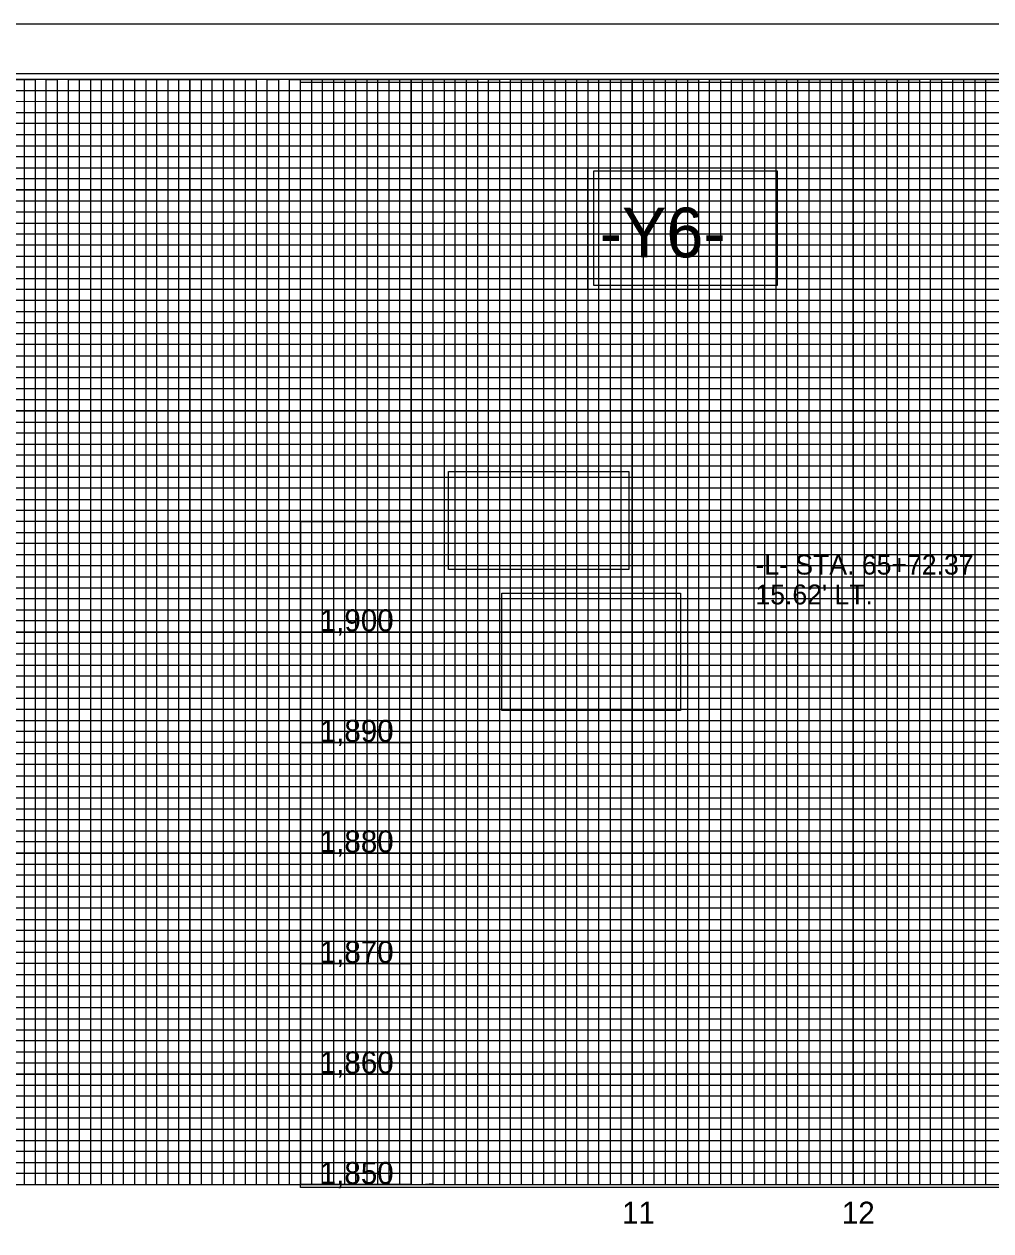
# Model space of a CAD drawing. Extents: x 557032 to 558716, y 525869 to 526969.
# Drawn here: x 557874 to 558312, y 526423 to 526969 of the extents above; entities that cross this region are included whole.
import ezdxf

# ---------------------------------------------------------------- set-up
doc = ezdxf.new("R2010")
doc.units = 0
for name, color, linetype in [('Exist Vertical Profile Horizontal Axis Label Major', 7, 'Continuous'), ('Exist Vertical Profile Vertical Axis Label', 7, 'Continuous'), ('Old_Level_63', 7, 'Continuous'), ('Prop Vertical Profile Curve Label', 7, 'Continuous'), ('Prop Vertical Profile Grade Label', 7, 'Continuous'), ('Prop VPI Label', 7, 'Continuous'), ('Scratch_Level_5', 7, 'Continuous'), ('Sheet Cutting Line CELL', 7, 'Continuous'), ('Sheet DOT Grid CELL', 7, 'Continuous'), ('Sheet Layout Profile Border Port 1', 7, 'Continuous'), ('Sheet Plot Border Inside CELL', 7, 'Continuous'), ('Sheet Plot Border Outside CELL', 7, 'Continuous'), ('Sheet Profile CELL', 7, 'Continuous'), ('Sheet Profile Grid Major CELL', 7, 'Continuous'), ('Sheet Profile Grid Middle CELL', 7, 'Continuous'), ('Sheet Profile Grid Minor CELL', 7, 'Continuous')]:
    doc.layers.add(name, color=color, linetype=linetype)

msp = doc.modelspace()

# ---------------------------------------------------------------- linework, layer by layer
at = {"layer": 'Old_Level_63'}
msp.add_lwpolyline([(557999.45, 526744.22), (558049.45, 526744.22), (558049.45, 526444.22), (557999.45, 526444.22)], close=True, dxfattribs=at)
at = {"layer": 'Prop Vertical Profile Curve Label'}
for points in [[(558132.11, 526902.85), (558215.04, 526902.85), (558215.04, 526850.91), (558132.11, 526850.91)], [(558132.11, 526902.85), (558215.04, 526902.85), (558215.04, 526850.91), (558132.11, 526850.91)], [(558066.42, 526766.81), (558148.02, 526766.81), (558148.02, 526722.46), (558066.42, 526722.46)], [(558090.5, 526711.86), (558171.26, 526711.86), (558171.26, 526658.64), (558090.5, 526658.64)]]:
    msp.add_lwpolyline(points, close=True, dxfattribs=at)
at = {"layer": 'Prop VPI Label'}
msp.add_lwpolyline([(558129.45, 526904.22), (558214.45, 526904.22), (558214.45, 526849.22), (558129.45, 526849.22)], close=True, dxfattribs=at)
at = {"layer": 'Scratch_Level_5'}
msp.add_lwpolyline([(557999.45, 526942.96), (558514.45, 526942.96), (558514.5, 526442.96), (557999.5, 526442.96)], close=True, dxfattribs=at)
at = {"layer": 'Sheet Cutting Line CELL'}
msp.add_line((558716.45, 526969.22), (557032.45, 526969.22), dxfattribs=at)
at = {"layer": 'Sheet DOT Grid CELL'}
for p, q in [((557899.45, 526444.22), (557899.45, 526944.22)), ((557949.45, 526444.22), (557949.45, 526944.22)), ((557999.45, 526444.22), (557999.45, 526944.22)), ((558049.45, 526444.22), (558049.45, 526944.22)), ((558099.45, 526444.22), (558099.45, 526944.22)), ((558149.45, 526444.22), (558149.45, 526944.22)), ((558199.45, 526444.22), (558199.45, 526944.22)), ((558249.45, 526444.22), (558249.45, 526944.22)), ((558299.45, 526444.22), (558299.45, 526944.22)), ((558499.4, 526894.22), (557199.45, 526894.22)), ((558499.4, 526844.22), (557199.45, 526844.22)), ((558499.45, 526794.22), (557199.45, 526794.22)), ((558699.45, 526694.22), (557199.45, 526694.22)), ((558699.45, 526644.22), (557199.45, 526644.22)), ((558699.45, 526594.22), (557199.45, 526594.22)), ((558699.45, 526544.22), (557199.45, 526544.22)), ((558699.45, 526494.22), (557199.45, 526494.22))]:
    msp.add_line(p, q, dxfattribs=at)
at = {"layer": 'Sheet Layout Profile Border Port 1'}
msp.add_lwpolyline([(557249.45, 526783.17), (557249.45, 526444.22), (558649.45, 526444.22), (558649.45, 526783.17)], dxfattribs=at)
at = {"layer": 'Sheet Plot Border Inside CELL'}
msp.add_lwpolyline([(557045.45, 525891.67), (558711.95, 525891.67), (558711.95, 526946.77), (557045.45, 526946.77)], close=True, dxfattribs=at)
at = {"layer": 'Sheet Plot Border Outside CELL'}
msp.add_lwpolyline([(557032.45, 525869.22), (558716.45, 525869.22), (558716.45, 526969.22), (557032.45, 526969.22)], close=True, dxfattribs=at)
at = {"layer": 'Sheet Profile CELL'}
msp.add_line((557199.45, 526444.22), (558699.45, 526444.22), dxfattribs=at)
msp.add_lwpolyline([(558699.45, 526944.22), (557199.45, 526944.22), (557199.45, 525894.22), (558699.45, 525894.22)], close=True, dxfattribs=at)
at = {"layer": 'Sheet Profile Grid Major CELL'}
for p, q in [((557999.45, 526694.22), (558049.45, 526694.22)), ((557999.45, 526644.22), (558049.45, 526644.22)), ((557999.45, 526594.22), (558049.45, 526594.22)), ((557999.45, 526544.22), (558049.45, 526544.22)), ((557999.45, 526494.22), (558049.45, 526494.22))]:
    msp.add_line(p, q, dxfattribs=at)
for points in [[(557849.45, 526444.22), (557899.45, 526444.22), (557899.45, 526944.22), (557949.45, 526944.22), (557949.45, 526444.22), (557999.45, 526444.22), (557999.45, 526944.22), (558049.45, 526944.22), (558049.45, 526444.22), (558099.45, 526444.22), (558099.45, 526944.22), (558149.45, 526944.22), (558149.45, 526444.22), (558199.45, 526444.22), (558199.45, 526944.22), (558249.45, 526944.22), (558249.45, 526444.22), (558299.45, 526444.22), (558299.45, 526944.22), (558349.45, 526944.22)], [(557199.45, 526894.22), (558499.45, 526894.22)], [(558499.45, 526844.22), (557199.45, 526844.22), (557199.45, 526794.22), (558499.45, 526794.22)], [(558699.45, 526744.22), (557199.45, 526744.22), (557199.45, 526694.22), (558699.45, 526694.22)], [(558699.45, 526644.22), (557199.45, 526644.22), (557199.45, 526594.22), (558699.45, 526594.22)], [(558699.45, 526544.22), (557199.45, 526544.22), (557199.45, 526544.22), (557199.45, 526494.22), (558699.45, 526494.22)]]:
    msp.add_lwpolyline(points, dxfattribs=at)
msp.add_lwpolyline([(557999.45, 526444.22), (558049.45, 526444.22), (558049.45, 526744.22), (557999.45, 526744.22)], close=True, dxfattribs=at)
at = {"layer": 'Sheet Profile Grid Middle CELL'}
msp.add_line((557199.45, 526919.22), (558499.4, 526919.22), dxfattribs=at)
for points in [[(557824.45, 526944.22), (557874.45, 526944.22), (557874.45, 526444.22), (557924.45, 526444.22), (557924.45, 526944.22), (557974.45, 526944.22), (557974.45, 526444.22), (558024.45, 526444.22), (558024.45, 526944.22), (558074.45, 526944.22), (558074.45, 526444.22), (558124.45, 526444.22), (558124.45, 526944.22), (558174.45, 526944.22), (558174.45, 526444.22), (558224.45, 526444.22), (558224.45, 526944.22), (558274.45, 526944.22), (558274.45, 526444.22), (558324.45, 526444.22)], [(558499.45, 526869.22), (557199.45, 526869.22), (557199.45, 526819.22), (558499.45, 526819.22)], [(558699.45, 526769.22), (557199.45, 526769.22), (557199.45, 526719.22), (558524.45, 526719.22)], [(558699.45, 526669.22), (557199.45, 526669.22), (557199.45, 526619.22), (558699.45, 526619.22)], [(558699.45, 526569.22), (557199.45, 526569.22), (557199.45, 526519.22), (558699.45, 526519.22)], [(558699.45, 526469.22), (557199.45, 526469.22)]]:
    msp.add_lwpolyline(points, dxfattribs=at)
at = {"layer": 'Sheet Profile Grid Minor CELL'}
for p, q in [((557249.45, 526939.22), (558499.45, 526939.22)), ((558499.45, 526934.22), (557249.45, 526933.87)), ((557249.45, 526929.22), (558499.45, 526929.22)), ((558499.4, 526809.22), (557249.45, 526809.22)), ((558499.45, 526804.22), (557249.45, 526804.22)), ((558499.45, 526799.22), (557249.45, 526799.22)), ((557249.45, 526789.22), (558499.45, 526789.22)), ((558499.45, 526784.22), (557249.45, 526784.22)), ((557249.45, 526779.22), (558649.45, 526779.22)), ((558649.45, 526759.22), (557249.45, 526759.22)), ((557249.45, 526754.22), (558649.45, 526754.22)), ((558649.45, 526734.22), (557249.45, 526734.22)), ((557249.45, 526729.22), (558649.45, 526729.22)), ((558649.45, 526709.22), (557249.45, 526709.22)), ((557249.45, 526704.22), (558649.45, 526704.22)), ((558649.45, 526699.22), (557249.45, 526699.22)), ((557249.45, 526689.22), (558649.45, 526689.22)), ((558649.45, 526684.22), (557249.45, 526684.22)), ((557249.45, 526679.22), (558649.45, 526679.22)), ((558649.45, 526674.22), (557249.45, 526674.22)), ((557249.45, 526664.22), (558649.45, 526664.22)), ((558649.45, 526659.22), (557249.45, 526659.22)), ((557249.45, 526654.22), (558649.45, 526654.22)), ((558649.45, 526649.22), (557249.45, 526649.22)), ((557249.45, 526639.22), (558649.45, 526639.22)), ((558649.45, 526634.22), (557249.45, 526634.22)), ((557249.45, 526629.22), (558649.45, 526629.22)), ((558649.45, 526624.22), (557249.45, 526624.22)), ((557249.45, 526614.22), (558649.45, 526614.22)), ((558649.45, 526609.22), (557249.45, 526609.22)), ((557249.45, 526604.22), (558649.45, 526604.22)), ((558649.45, 526599.22), (557249.45, 526599.22)), ((557249.45, 526589.22), (558649.45, 526589.22)), ((558649.45, 526584.22), (557249.45, 526584.22)), ((557249.45, 526579.22), (558649.45, 526579.22)), ((558649.45, 526574.22), (557249.45, 526574.22)), ((557249.45, 526564.22), (558649.45, 526564.22)), ((558649.45, 526559.22), (557249.45, 526559.22)), ((558649.45, 526554.22), (557249.45, 526554.22)), ((558649.45, 526549.22), (557249.45, 526549.22)), ((557249.45, 526539.22), (558649.45, 526539.22)), ((558649.45, 526534.22), (557249.45, 526534.22)), ((557249.45, 526529.22), (558649.45, 526529.22)), ((558649.45, 526524.22), (557249.45, 526524.22)), ((557249.45, 526514.22), (558649.45, 526514.22)), ((558649.45, 526509.22), (557249.45, 526509.22)), ((557249.45, 526504.22), (558649.45, 526504.22)), ((558649.45, 526499.22), (557249.45, 526499.22)), ((557249.45, 526489.22), (558649.45, 526489.22)), ((558649.45, 526484.22), (557249.45, 526484.22)), ((557249.45, 526479.22), (558649.45, 526479.22)), ((558649.45, 526474.22), (557249.45, 526474.22)), ((557249.45, 526464.22), (558649.45, 526464.22)), ((558649.45, 526459.22), (557249.45, 526459.22)), ((557249.45, 526454.22), (558649.45, 526454.22))]:
    msp.add_line(p, q, dxfattribs=at)
for points in [[(557869.45, 526944.22), (557879.45, 526944.22), (557879.45, 526444.22), (557884.45, 526444.22), (557884.45, 526944.22), (557889.45, 526944.22), (557889.45, 526444.22), (557894.45, 526444.22), (557894.45, 526944.22), (557904.45, 526944.22), (557904.45, 526444.22), (557904.45, 526444.22), (557909.45, 526444.22), (557909.45, 526944.22), (557914.45, 526944.22), (557914.45, 526444.22), (557919.45, 526444.22), (557919.45, 526944.22), (557929.45, 526944.22), (557929.45, 526444.22), (557934.45, 526444.22), (557934.45, 526944.22), (557939.45, 526944.22), (557939.45, 526444.22), (557944.45, 526444.22), (557944.45, 526944.22), (557954.45, 526944.22), (557954.45, 526444.22), (557959.45, 526444.22), (557959.45, 526944.22), (557964.45, 526944.22), (557964.45, 526444.22), (557969.45, 526444.22), (557969.45, 526944.22), (557979.45, 526944.22), (557979.45, 526444.22), (557984.45, 526444.22), (557984.45, 526944.22), (557989.45, 526944.22), (557989.45, 526444.22), (557994.45, 526444.22), (557994.45, 526944.22), (558004.45, 526944.22), (558004.45, 526444.22), (558009.45, 526444.22), (558009.45, 526944.22), (558014.45, 526944.22), (558014.45, 526444.22), (558019.45, 526444.22), (558019.45, 526944.22), (558029.45, 526944.22), (558029.45, 526444.22), (558034.45, 526444.22), (558034.45, 526944.22), (558039.45, 526944.22), (558039.45, 526444.22), (558044.45, 526444.22), (558044.45, 526944.22), (558054.45, 526944.22), (558054.45, 526444.22), (558059.15, 526444.77), (558059.45, 526444.22), (558059.45, 526944.22), (558064.45, 526944.22), (558064.45, 526444.22), (558069.45, 526444.22), (558069.45, 526944.22), (558079.45, 526944.22), (558079.45, 526444.22), (558084.45, 526444.22)], [(558084.45, 526444.22), (558084.45, 526944.22), (558089.45, 526944.22), (558089.45, 526444.22), (558094.45, 526444.22), (558094.45, 526944.22), (558104.45, 526944.22), (558104.45, 526444.22), (558109.45, 526444.22), (558109.45, 526944.22), (558114.45, 526944.22), (558114.45, 526444.22), (558119.45, 526444.22), (558119.45, 526944.22), (558129.45, 526944.22), (558129.45, 526444.22), (558134.45, 526444.22), (558134.45, 526944.22), (558139.45, 526944.22), (558139.45, 526444.22), (558144.45, 526444.22), (558144.45, 526944.22), (558154.45, 526944.22), (558154.45, 526444.22), (558159.45, 526444.22), (558159.45, 526944.22), (558164.45, 526944.22), (558164.45, 526444.22), (558169.45, 526444.22), (558169.45, 526944.22), (558179.45, 526944.22), (558179.45, 526444.22), (558184.45, 526444.22), (558184.45, 526944.22), (558189.45, 526944.22), (558189.45, 526444.22), (558194.45, 526444.22), (558194.45, 526944.22), (558204.45, 526944.22), (558204.45, 526444.22), (558209.45, 526444.22), (558209.45, 526944.22), (558214.45, 526944.22), (558214.45, 526444.22), (558219.45, 526444.22), (558219.45, 526944.22), (558229.45, 526944.22), (558229.45, 526444.22), (558234.45, 526444.22), (558234.45, 526944.22), (558239.45, 526944.22), (558239.45, 526444.22), (558244.45, 526444.22), (558244.45, 526944.22), (558254.45, 526944.22), (558254.45, 526444.22), (558259.45, 526444.22), (558259.45, 526944.22), (558264.45, 526944.22), (558264.45, 526444.22), (558269.45, 526444.22), (558269.45, 526944.22), (558279.45, 526944.22), (558279.45, 526444.22), (558284.45, 526444.22), (558284.45, 526944.22), (558289.45, 526944.22), (558289.45, 526444.22), (558294.45, 526444.22), (558294.45, 526944.22), (558304.45, 526944.22), (558304.45, 526444.22), (558309.45, 526444.22), (558309.45, 526944.22), (558314.45, 526944.22)], [(558499.45, 526924.22), (557249.45, 526924.22), (557249.45, 526914.22), (558499.45, 526914.22)], [(558499.4, 526909.22), (557249.45, 526909.22), (557249.45, 526904.22), (558499.45, 526904.22)], [(558499.45, 526899.22), (557249.45, 526899.22), (557249.45, 526889.22), (558499.45, 526889.22)], [(558499.45, 526884.22), (557249.45, 526884.22), (557249.45, 526879.22), (558499.45, 526879.22)], [(558499.45, 526874.22), (557249.45, 526874.22), (557249.45, 526864.22), (558499.45, 526864.22)], [(558499.45, 526859.22), (557249.45, 526859.22), (557249.45, 526854.22), (558499.45, 526854.22)], [(558499.45, 526849.22), (557249.45, 526849.22), (557249.45, 526839.22), (558499.45, 526839.22)], [(558499.45, 526834.12), (557249.55, 526834.12), (557249.55, 526829.22), (558499.45, 526829.22)], [(558499.45, 526824.22), (557249.45, 526824.22), (557249.45, 526814.22), (558499.45, 526814.22)], [(558649.45, 526774.22), (557249.45, 526774.22), (557249.45, 526764.22), (558649.45, 526764.22)], [(558649.45, 526749.22), (557249.45, 526749.22), (557249.45, 526739.22), (558649.45, 526739.22)], [(558649.45, 526724.22), (557249.45, 526724.22), (557249.45, 526714.22), (558649.45, 526714.22)], [(558649.45, 526449.22), (557249.45, 526449.22)]]:
    msp.add_lwpolyline(points, dxfattribs=at)

# ---------------------------------------------------------------- texts
at = {"layer": 'Exist Vertical Profile Horizontal Axis Label Major'}
for s, p in [('11', (558144.88, 526426.49)), ('12', (558244.31, 526426.49))]:
    msp.add_text(s, height=10, dxfattribs=at).set_placement(p)
at = {"layer": 'Exist Vertical Profile Vertical Axis Label'}
for s, p in [('1,900', (558008.15, 526694.47)), ('1,890', (558008.15, 526644.47)), ('1,880', (558008.15, 526594.47)), ('1,870', (558008.15, 526544.47)), ('1,860', (558008.15, 526494.47)), ('1,850', (558008.15, 526444.47))]:
    msp.add_text(s, height=10, dxfattribs=at).set_placement(p)
at = {"layer": 'Prop Vertical Profile Grade Label'}
msp.add_text('-Y6-', height=22.5, dxfattribs=at).set_placement((558134.86, 526863.71))
at = {"layer": 'Prop VPI Label'}
for s, p in [('-L- STA. 65+72.37', (558205.22, 526720.2)), ("15.62' LT.", (558205.22, 526706.7))]:
    msp.add_text(s, height=9, dxfattribs=at).set_placement(p)

doc.saveas('drawing.dxf')
